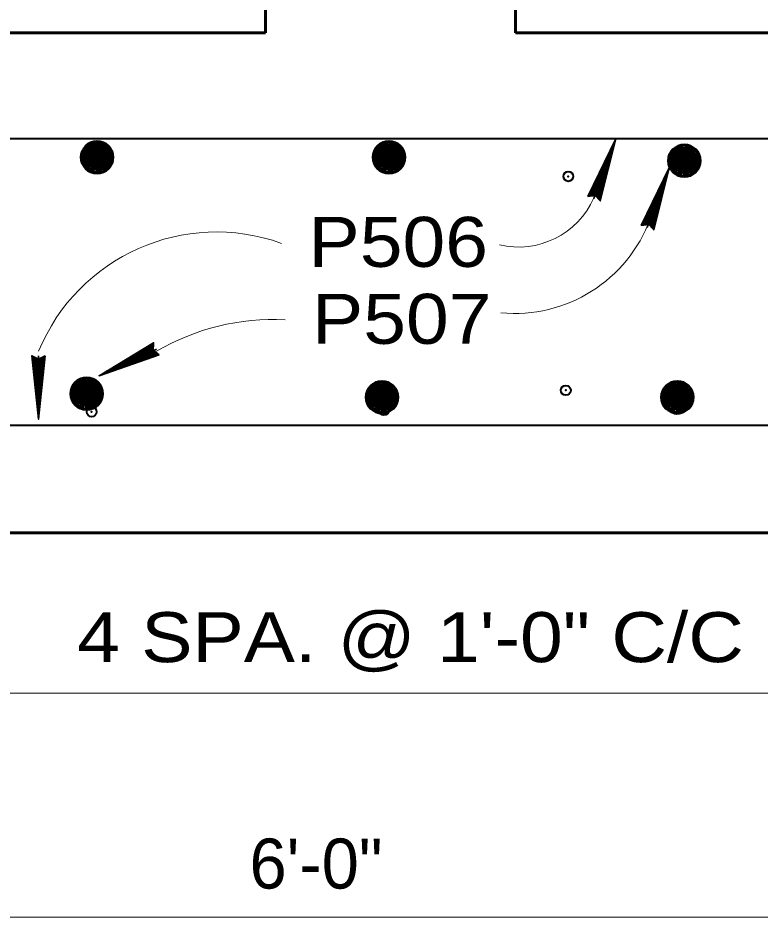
# Model space of a CAD drawing. Extents: x 14.14 to 17.34, y -1.61 to 0.38.
# Drawn here: x 15.611 to 15.7348, y -0.0793 to 0.0707 of the extents above; entities that cross this region are included whole.
import ezdxf

# ---------------------------------------------------------------- set-up
doc = ezdxf.new("R2010")
doc.units = 0
doc.header["$LTSCALE"] = 0.0033
doc.header["$PDMODE"] = 32
doc.header["$PDSIZE"] = 0.00165
doc.layers.add('1', color=7, linetype='Continuous', lineweight=40)

msp = doc.modelspace()

# ---------------------------------------------------------------- linework, layer by layer
at = {"layer": '1', "lineweight": 60}
for p, q in [((15.589833, 0.068167), (15.652333, 0.068167)), ((15.7565, 0.068167), (15.694, 0.068167)), ((15.622417, 0.049), (15.62225, 0.046083)), ((15.622667, 0.049), (15.622417, 0.046083)), ((15.622833, 0.049), (15.622667, 0.046)), ((15.623, 0.049), (15.62275, 0.046)), ((15.623167, 0.049), (15.623, 0.046)), ((15.623417, 0.049), (15.62325, 0.046)), ((15.623667, 0.049), (15.623417, 0.046)), ((15.62375, 0.048917), (15.623583, 0.046)), ((15.623917, 0.048917), (15.62375, 0.046)), ((15.624083, 0.048917), (15.623917, 0.046)), ((15.624333, 0.048917), (15.624083, 0.046)), ((15.6245, 0.048917), (15.624333, 0.046)), ((15.62475, 0.048833), (15.6245, 0.045917)), ((15.625, 0.048833), (15.62475, 0.045917)), ((15.625167, 0.048833), (15.625, 0.045917)), ((15.62525, 0.048833), (15.625083, 0.045917)), ((15.625417, 0.048833), (15.62525, 0.045917)), ((15.6255, 0.048833), (15.625333, 0.045917)), ((15.62575, 0.04875), (15.6255, 0.045833)), ((15.625917, 0.04875), (15.62575, 0.045833)), ((15.626083, 0.04875), (15.625833, 0.045833)), ((15.62625, 0.04875), (15.626083, 0.045833)), ((15.6265, 0.04875), (15.626333, 0.045833)), ((15.62675, 0.046833), (15.626583, 0.048667)), ((15.671083, 0.049), (15.670917, 0.046083)), ((15.671333, 0.049), (15.671083, 0.046083)), ((15.6715, 0.049), (15.671333, 0.046)), ((15.671667, 0.049), (15.671417, 0.046)), ((15.671833, 0.049), (15.671667, 0.046)), ((15.672083, 0.049), (15.671917, 0.046)), ((15.672333, 0.049), (15.672083, 0.046)), ((15.672417, 0.048917), (15.67225, 0.046)), ((15.672583, 0.048917), (15.672417, 0.046)), ((15.67275, 0.048917), (15.672583, 0.046)), ((15.673, 0.048917), (15.67275, 0.046)), ((15.673167, 0.048917), (15.673, 0.046)), ((15.673417, 0.048833), (15.673167, 0.045917)), ((15.673667, 0.048833), (15.673417, 0.045917)), ((15.673833, 0.048833), (15.673667, 0.045917)), ((15.673917, 0.048833), (15.67375, 0.045917)), ((15.674083, 0.048833), (15.673917, 0.045917)), ((15.674167, 0.048833), (15.674, 0.045917)), ((15.674417, 0.04875), (15.674167, 0.045833)), ((15.674583, 0.04875), (15.674417, 0.045833)), ((15.67475, 0.04875), (15.6745, 0.045833)), ((15.674917, 0.04875), (15.67475, 0.045833)), ((15.675167, 0.04875), (15.675, 0.045833)), ((15.675417, 0.046833), (15.67525, 0.048667)), ((15.720333, 0.048417), (15.720167, 0.0455)), ((15.720583, 0.048417), (15.720333, 0.0455)), ((15.72075, 0.048417), (15.720583, 0.045417)), ((15.720917, 0.048417), (15.720667, 0.045417)), ((15.721083, 0.048417), (15.720917, 0.045417)), ((15.721333, 0.048417), (15.721167, 0.045417)), ((15.721583, 0.048417), (15.721333, 0.045417)), ((15.721667, 0.048333), (15.7215, 0.045417)), ((15.721833, 0.048333), (15.721667, 0.045417)), ((15.722, 0.048333), (15.721833, 0.045417)), ((15.72225, 0.048333), (15.722, 0.045417)), ((15.722417, 0.048333), (15.72225, 0.045417)), ((15.722667, 0.04825), (15.722417, 0.045333)), ((15.722917, 0.04825), (15.722667, 0.045333)), ((15.723083, 0.04825), (15.722917, 0.045333)), ((15.723167, 0.04825), (15.723, 0.045333)), ((15.723333, 0.04825), (15.723167, 0.045333)), ((15.723417, 0.04825), (15.72325, 0.045333)), ((15.723667, 0.048167), (15.723417, 0.04525)), ((15.723833, 0.048167), (15.723667, 0.04525)), ((15.724, 0.048167), (15.72375, 0.04525)), ((15.724167, 0.048167), (15.724, 0.04525)), ((15.724417, 0.048167), (15.72425, 0.04525)), ((15.724667, 0.04625), (15.7245, 0.048083)), ((15.62675, 0.046833), (15.622, 0.046083)), ((15.675417, 0.046833), (15.670667, 0.046083)), ((15.724667, 0.04625), (15.719917, 0.0455)), ((15.620667, 0.009583), (15.6205, 0.006667)), ((15.620917, 0.009583), (15.620667, 0.006667)), ((15.621083, 0.009583), (15.620917, 0.006583)), ((15.62125, 0.009583), (15.621, 0.006583)), ((15.621417, 0.009583), (15.62125, 0.006583)), ((15.621667, 0.009583), (15.6215, 0.006583)), ((15.621917, 0.009583), (15.621667, 0.006583)), ((15.622, 0.0095), (15.621833, 0.006583)), ((15.622167, 0.0095), (15.622, 0.006583)), ((15.622333, 0.0095), (15.622167, 0.006583)), ((15.622583, 0.0095), (15.622333, 0.006583)), ((15.62275, 0.0095), (15.622583, 0.006583)), ((15.623, 0.009417), (15.62275, 0.0065)), ((15.62325, 0.009417), (15.623, 0.0065)), ((15.623417, 0.009417), (15.62325, 0.0065)), ((15.6235, 0.009417), (15.623333, 0.0065)), ((15.623667, 0.009417), (15.6235, 0.0065)), ((15.62375, 0.009417), (15.623583, 0.0065)), ((15.624, 0.009333), (15.62375, 0.006417)), ((15.624167, 0.009333), (15.624, 0.006417)), ((15.624333, 0.009333), (15.624083, 0.006417)), ((15.6245, 0.009333), (15.624333, 0.006417)), ((15.62475, 0.009333), (15.624583, 0.006417)), ((15.625, 0.007417), (15.624833, 0.00925)), ((15.669917, 0.009), (15.66975, 0.006083)), ((15.670167, 0.009), (15.669917, 0.006083)), ((15.670333, 0.009), (15.670167, 0.006)), ((15.6705, 0.009), (15.67025, 0.006)), ((15.670667, 0.009), (15.6705, 0.006)), ((15.670917, 0.009), (15.67075, 0.006)), ((15.671167, 0.009), (15.670917, 0.006)), ((15.719167, 0.009), (15.719, 0.006083)), ((15.719417, 0.009), (15.719167, 0.006083)), ((15.719583, 0.009), (15.719417, 0.006)), ((15.71975, 0.009), (15.7195, 0.006)), ((15.719917, 0.009), (15.71975, 0.006)), ((15.720167, 0.009), (15.72, 0.006)), ((15.720417, 0.009), (15.720167, 0.006)), ((15.67125, 0.008917), (15.671083, 0.006)), ((15.671417, 0.008917), (15.67125, 0.006)), ((15.671583, 0.008917), (15.671417, 0.006)), ((15.671833, 0.008917), (15.671583, 0.006)), ((15.672, 0.008917), (15.671833, 0.006)), ((15.67225, 0.008833), (15.672, 0.005917)), ((15.6725, 0.008833), (15.67225, 0.005917)), ((15.672667, 0.008833), (15.6725, 0.005917)), ((15.67275, 0.008833), (15.672583, 0.005917)), ((15.672917, 0.008833), (15.67275, 0.005917)), ((15.673, 0.008833), (15.672833, 0.005917)), ((15.67325, 0.00875), (15.673, 0.005833)), ((15.673417, 0.00875), (15.67325, 0.005833)), ((15.673583, 0.00875), (15.673333, 0.005833)), ((15.67375, 0.00875), (15.673583, 0.005833)), ((15.674, 0.00875), (15.673833, 0.005833)), ((15.67425, 0.006833), (15.674083, 0.008667)), ((15.7205, 0.008917), (15.720333, 0.006)), ((15.720667, 0.008917), (15.7205, 0.006)), ((15.720833, 0.008917), (15.720667, 0.006)), ((15.721083, 0.008917), (15.720833, 0.006)), ((15.72125, 0.008917), (15.721083, 0.006)), ((15.7215, 0.008833), (15.72125, 0.005917)), ((15.72175, 0.008833), (15.7215, 0.005917)), ((15.721917, 0.008833), (15.72175, 0.005917)), ((15.722, 0.008833), (15.721833, 0.005917)), ((15.722167, 0.008833), (15.722, 0.005917)), ((15.72225, 0.008833), (15.722083, 0.005917)), ((15.7225, 0.00875), (15.72225, 0.005833)), ((15.722667, 0.00875), (15.7225, 0.005833)), ((15.722833, 0.00875), (15.722583, 0.005833)), ((15.723, 0.00875), (15.722833, 0.005833)), ((15.72325, 0.00875), (15.723083, 0.005833)), ((15.7235, 0.006833), (15.723333, 0.008667)), ((15.625, 0.007417), (15.62025, 0.006667)), ((15.67425, 0.006833), (15.6695, 0.006083)), ((15.7235, 0.006833), (15.71875, 0.006083))]:
    msp.add_line(p, q, dxfattribs=at)
at = {"layer": '1'}
for p, q in [((15.524417, 0.050583), (15.822167, 0.050583)), ((15.6245, 0.0485), (15.625833, 0.0495)), ((15.626583, 0.048667), (15.625333, 0.049833)), ((15.673167, 0.0485), (15.6745, 0.0495)), ((15.67525, 0.048667), (15.674, 0.049833)), ((15.622167, 0.049), (15.62675, 0.046833)), ((15.622333, 0.048), (15.626167, 0.047333)), ((15.622417, 0.048583), (15.626333, 0.047833)), ((15.622417, 0.048417), (15.626333, 0.047667)), ((15.622417, 0.048167), (15.62625, 0.047417)), ((15.6225, 0.049), (15.626417, 0.048333)), ((15.6225, 0.048833), (15.626417, 0.048083)), ((15.622583, 0.049333), (15.626417, 0.048667)), ((15.670833, 0.049), (15.675417, 0.046833)), ((15.671, 0.048), (15.674833, 0.047333)), ((15.671083, 0.048583), (15.675, 0.047833)), ((15.671083, 0.048417), (15.675, 0.047667)), ((15.671083, 0.048167), (15.674917, 0.047417)), ((15.671167, 0.049), (15.675083, 0.048333)), ((15.671167, 0.048833), (15.675083, 0.048083)), ((15.67125, 0.049333), (15.675083, 0.048667)), ((15.720083, 0.048417), (15.724667, 0.04625)), ((15.720333, 0.048), (15.72425, 0.04725)), ((15.720417, 0.048417), (15.724333, 0.04775)), ((15.720417, 0.04825), (15.724333, 0.0475)), ((15.7205, 0.04875), (15.724333, 0.048083)), ((15.722417, 0.047917), (15.72375, 0.048917)), ((15.7245, 0.048083), (15.72325, 0.04925)), ((15.622083, 0.04675), (15.626, 0.046)), ((15.622083, 0.046583), (15.625917, 0.045833)), ((15.622167, 0.047167), (15.626083, 0.046417)), ((15.62225, 0.047583), (15.626083, 0.046833)), ((15.62225, 0.047417), (15.626083, 0.046667)), ((15.622333, 0.047833), (15.626167, 0.047083)), ((15.67075, 0.04675), (15.674667, 0.046)), ((15.67075, 0.046583), (15.674583, 0.045833)), ((15.670833, 0.047167), (15.67475, 0.046417)), ((15.670917, 0.047583), (15.67475, 0.046833)), ((15.670917, 0.047417), (15.67475, 0.046667)), ((15.671, 0.047833), (15.674833, 0.047083)), ((15.720083, 0.046583), (15.724, 0.045833)), ((15.720167, 0.047), (15.724, 0.04625)), ((15.720167, 0.046833), (15.724, 0.046083)), ((15.72025, 0.047417), (15.724083, 0.04675)), ((15.72025, 0.04725), (15.724083, 0.0465)), ((15.720333, 0.047833), (15.72425, 0.047083)), ((15.720333, 0.047583), (15.724167, 0.046833)), ((15.622, 0.04625), (15.625833, 0.0455)), ((15.622, 0.046083), (15.625833, 0.045333)), ((15.622083, 0.046333), (15.625917, 0.045667)), ((15.626333, 0.045833), (15.622583, 0.045417)), ((15.670667, 0.04625), (15.6745, 0.0455)), ((15.670667, 0.046083), (15.6745, 0.045333)), ((15.67075, 0.046333), (15.674583, 0.045667)), ((15.675, 0.045833), (15.67125, 0.045417)), ((15.719917, 0.045667), (15.72375, 0.044917)), ((15.719917, 0.0455), (15.72375, 0.04475)), ((15.72, 0.046167), (15.723917, 0.045417)), ((15.72, 0.046), (15.723833, 0.04525)), ((15.72, 0.04575), (15.723833, 0.045083)), ((15.72425, 0.04525), (15.7205, 0.044833)), ((15.620417, 0.009583), (15.625, 0.007417)), ((15.620667, 0.009167), (15.624583, 0.008417)), ((15.620667, 0.009), (15.624583, 0.00825)), ((15.62075, 0.009583), (15.624667, 0.008917)), ((15.62075, 0.009417), (15.624667, 0.008667)), ((15.620833, 0.009917), (15.624667, 0.00925)), ((15.62275, 0.009083), (15.624083, 0.010083)), ((15.624833, 0.00925), (15.623583, 0.010417)), ((15.669667, 0.009), (15.67425, 0.006833)), ((15.67, 0.009), (15.673917, 0.008333)), ((15.670083, 0.009333), (15.673917, 0.008667)), ((15.672, 0.0085), (15.673333, 0.0095)), ((15.674083, 0.008667), (15.672833, 0.009833)), ((15.718917, 0.009), (15.7235, 0.006833)), ((15.71925, 0.009), (15.723167, 0.008333)), ((15.719333, 0.009333), (15.723167, 0.008667)), ((15.72125, 0.0085), (15.722583, 0.0095)), ((15.723333, 0.008667), (15.722083, 0.009833)), ((15.620417, 0.00775), (15.624333, 0.007)), ((15.6205, 0.008167), (15.624333, 0.007417)), ((15.6205, 0.008), (15.624333, 0.00725)), ((15.620583, 0.008583), (15.624417, 0.007917)), ((15.620583, 0.008417), (15.624417, 0.007667)), ((15.620667, 0.00875), (15.6245, 0.008)), ((15.66975, 0.007583), (15.673583, 0.006833)), ((15.669833, 0.008), (15.673667, 0.007333)), ((15.669833, 0.007833), (15.673667, 0.007083)), ((15.669917, 0.008583), (15.673833, 0.007833)), ((15.669917, 0.008417), (15.673833, 0.007667)), ((15.669917, 0.008167), (15.67375, 0.007417)), ((15.67, 0.008833), (15.673917, 0.008083)), ((15.719, 0.007583), (15.722833, 0.006833)), ((15.719083, 0.008), (15.722917, 0.007333)), ((15.719083, 0.007833), (15.722917, 0.007083)), ((15.719167, 0.008583), (15.723083, 0.007833)), ((15.719167, 0.008417), (15.723083, 0.007667)), ((15.719167, 0.008167), (15.723, 0.007417)), ((15.71925, 0.008833), (15.723167, 0.008083)), ((15.62025, 0.006833), (15.624083, 0.006083)), ((15.62025, 0.006667), (15.624083, 0.005917)), ((15.620333, 0.007333), (15.62425, 0.006583)), ((15.620333, 0.007167), (15.624167, 0.006417)), ((15.620333, 0.006917), (15.624167, 0.00625)), ((15.624583, 0.006417), (15.620833, 0.006)), ((15.6695, 0.00625), (15.673333, 0.0055)), ((15.6695, 0.006083), (15.673333, 0.005333)), ((15.669583, 0.00675), (15.6735, 0.006)), ((15.669583, 0.006583), (15.673417, 0.005833)), ((15.669583, 0.006333), (15.673417, 0.005667)), ((15.669667, 0.007167), (15.673583, 0.006417)), ((15.66975, 0.007417), (15.673583, 0.006667)), ((15.71875, 0.00625), (15.722583, 0.0055)), ((15.71875, 0.006083), (15.722583, 0.005333)), ((15.718833, 0.00675), (15.72275, 0.006)), ((15.718833, 0.006583), (15.722667, 0.005833)), ((15.718833, 0.006333), (15.722667, 0.005667)), ((15.718917, 0.007167), (15.722833, 0.006417)), ((15.719, 0.007417), (15.722833, 0.006667)), ((15.673833, 0.005833), (15.670083, 0.005417)), ((15.723083, 0.005833), (15.719333, 0.005417)), ((15.52425, 0.00275), (15.821917, 0.00275))]:
    msp.add_line(p, q, dxfattribs=at)
at = {"layer": '1', "lineweight": 35}
for p, q in [((15.707083, 0.040583), (15.71075, 0.0505)), ((15.70625, 0.041083), (15.70975, 0.048167)), ((15.70625, 0.041083), (15.70975, 0.048167)), ((15.706333, 0.041083), (15.70975, 0.048167)), ((15.706417, 0.041083), (15.709833, 0.048167)), ((15.706417, 0.041083), (15.71, 0.048083)), ((15.70775, 0.0405), (15.709583, 0.047583)), ((15.708, 0.0405), (15.709667, 0.047667)), ((15.708, 0.0405), (15.709833, 0.047583)), ((15.708167, 0.040417), (15.709917, 0.047583)), ((15.716, 0.03575), (15.719667, 0.045667)), ((15.715167, 0.03625), (15.718667, 0.043333)), ((15.715167, 0.03625), (15.718667, 0.043333)), ((15.71525, 0.03625), (15.718667, 0.043333)), ((15.715333, 0.03625), (15.71875, 0.043333)), ((15.715333, 0.03625), (15.718917, 0.04325)), ((15.716667, 0.035667), (15.7185, 0.04275)), ((15.716917, 0.035667), (15.718583, 0.042833)), ((15.716917, 0.035667), (15.71875, 0.04275)), ((15.717083, 0.035583), (15.718833, 0.04275)), ((15.634167, 0.015417), (15.624583, 0.011)), ((15.6335, 0.016333), (15.627167, 0.0125)), ((15.6335, 0.016167), (15.627167, 0.012417)), ((15.633583, 0.016083), (15.62725, 0.01225)), ((15.63375, 0.016), (15.627417, 0.01225)), ((15.613417, 0.014083), (15.61425, 0.00675)), ((15.613583, 0.014083), (15.614333, 0.00675)), ((15.613667, 0.014083), (15.6145, 0.00675)), ((15.613833, 0.014167), (15.614583, 0.006833)), ((15.615333, 0.014083), (15.614333, 0.00625)), ((15.6145, 0.014333), (15.6145, 0.00375)), ((15.615333, 0.014083), (15.6145, 0.00625)), ((15.6155, 0.014083), (15.614583, 0.00625)), ((15.6155, 0.014083), (15.614583, 0.00625)), ((15.615417, 0.014083), (15.614583, 0.00625)), ((15.63425, 0.014583), (15.62675, 0.012167)), ((15.63425, 0.014583), (15.626833, 0.012)), ((15.634333, 0.0145), (15.626833, 0.012)), ((15.634333, 0.014417), (15.626833, 0.012)), ((15.634333, 0.014417), (15.626833, 0.012))]:
    msp.add_line(p, q, dxfattribs=at)
at = {"layer": '1', "lineweight": 13}
for p, q in [((15.523583, -0.041917), (15.820833, -0.041917)), ((15.511083, -0.07925), (15.837333, -0.07925))]:
    msp.add_line(p, q, dxfattribs=at)
at = {"layer": '1', "lineweight": 60}
for points in [[(15.652333, 0.068167), (15.652333, 0.089), (15.694, 0.089), (15.694, 0.068167)], [(15.839833, 0.068167), (15.839833, -0.015167), (15.5065, -0.015167)], [(15.625833, 0.045333), (15.625833, 0.0495), (15.624167, 0.044833), (15.624667, 0.05), (15.622583, 0.045417), (15.623333, 0.049917), (15.624917, 0.044917), (15.62175, 0.04825), (15.626583, 0.048667), (15.623333, 0.045), (15.625333, 0.049833), (15.622167, 0.049), (15.622, 0.046083)], [(15.622583, 0.045417), (15.624083, 0.047667), (15.621917, 0.048583), (15.623917, 0.05), (15.624083, 0.04775), (15.62575, 0.045417), (15.62175, 0.04775), (15.6245, 0.0485)], [(15.625333, 0.049833), (15.624083, 0.047667), (15.626333, 0.045833)], [(15.6745, 0.045333), (15.6745, 0.0495), (15.672833, 0.044833), (15.673333, 0.05), (15.67125, 0.045417), (15.672, 0.049917), (15.673583, 0.044917), (15.670417, 0.04825), (15.67525, 0.048667), (15.672, 0.045), (15.674, 0.049833), (15.670833, 0.049), (15.670667, 0.046083)], [(15.67125, 0.045417), (15.67275, 0.047667), (15.670583, 0.048583), (15.672583, 0.05), (15.67275, 0.04775), (15.674417, 0.045417), (15.670417, 0.04775), (15.673167, 0.0485)], [(15.674, 0.049833), (15.67275, 0.047667), (15.675, 0.045833)], [(15.621583, 0.047333), (15.62675, 0.048), (15.622167, 0.049)], [(15.67025, 0.047333), (15.675417, 0.048), (15.670833, 0.049)], [(15.7195, 0.04675), (15.724667, 0.047417), (15.720083, 0.048417)], [(15.72375, 0.04475), (15.72375, 0.048917), (15.722083, 0.04425), (15.722583, 0.049417), (15.7205, 0.044833), (15.72125, 0.049333), (15.722833, 0.044333), (15.719667, 0.047667), (15.7245, 0.048083), (15.72125, 0.044417), (15.72325, 0.04925), (15.720083, 0.048417), (15.719917, 0.0455)], [(15.7205, 0.044833), (15.722, 0.047083), (15.719833, 0.048), (15.721833, 0.049417), (15.722, 0.047167), (15.723667, 0.044833), (15.719667, 0.047167), (15.722417, 0.047917)], [(15.72325, 0.04925), (15.722, 0.047083), (15.72425, 0.04525)], [(15.624083, 0.005917), (15.624083, 0.010083), (15.622417, 0.005417), (15.622917, 0.010583), (15.620833, 0.006), (15.621583, 0.0105), (15.623167, 0.0055), (15.62, 0.008833), (15.624833, 0.00925), (15.621583, 0.005583), (15.623583, 0.010417), (15.620417, 0.009583), (15.62025, 0.006667)], [(15.620833, 0.006), (15.622333, 0.00825), (15.620167, 0.009167), (15.622167, 0.010583), (15.622333, 0.008333), (15.624, 0.006), (15.62, 0.008333), (15.62275, 0.009083)], [(15.619833, 0.007917), (15.625, 0.008583), (15.620417, 0.009583)], [(15.623583, 0.010417), (15.622333, 0.00825), (15.624583, 0.006417)], [(15.669083, 0.007333), (15.67425, 0.008), (15.669667, 0.009)], [(15.673333, 0.005333), (15.673333, 0.0095), (15.671667, 0.004833), (15.672167, 0.01), (15.670083, 0.005417), (15.670833, 0.009917), (15.672417, 0.004917), (15.66925, 0.00825), (15.674083, 0.008667), (15.670833, 0.005), (15.672833, 0.009833), (15.669667, 0.009), (15.6695, 0.006083)], [(15.670083, 0.005417), (15.671583, 0.007667), (15.669417, 0.008583), (15.671417, 0.01), (15.671583, 0.00775), (15.67325, 0.005417), (15.66925, 0.00775), (15.672, 0.0085)], [(15.672833, 0.009833), (15.671583, 0.007667), (15.673833, 0.005833)], [(15.718333, 0.007333), (15.7235, 0.008), (15.718917, 0.009)], [(15.722583, 0.005333), (15.722583, 0.0095), (15.720917, 0.004833), (15.721417, 0.01), (15.719333, 0.005417), (15.720083, 0.009917), (15.721667, 0.004917), (15.7185, 0.00825), (15.723333, 0.008667), (15.720083, 0.005), (15.722083, 0.009833), (15.718917, 0.009), (15.71875, 0.006083)], [(15.719333, 0.005417), (15.720833, 0.007667), (15.718667, 0.008583), (15.720667, 0.01), (15.720833, 0.00775), (15.7225, 0.005417), (15.7185, 0.00775), (15.72125, 0.0085)], [(15.722083, 0.009833), (15.720833, 0.007667), (15.723083, 0.005833)]]:
    msp.add_lwpolyline(points, dxfattribs=at)
at = {"layer": '1', "lineweight": 35}
for points in [[(15.706083, 0.040917), (15.71075, 0.0505), (15.708167, 0.040167), (15.707333, 0.041083)], [(15.70725, 0.04125), (15.70875, 0.045667), (15.708833, 0.045667), (15.708583, 0.044833), (15.707167, 0.041333), (15.708167, 0.044167), (15.707, 0.04125), (15.707667, 0.043333), (15.706833, 0.04125), (15.70825, 0.0445), (15.71, 0.048833), (15.709917, 0.047833), (15.710333, 0.049), (15.7075, 0.041167), (15.7085, 0.043417), (15.707583, 0.041), (15.709, 0.046167), (15.707833, 0.040917)], [(15.715, 0.036083), (15.719667, 0.045667), (15.717083, 0.035333), (15.71625, 0.03625)], [(15.716167, 0.036417), (15.717667, 0.040833), (15.71775, 0.040833), (15.7175, 0.04), (15.716083, 0.0365), (15.717083, 0.039333), (15.715917, 0.036417), (15.716583, 0.0385), (15.71575, 0.036417), (15.717167, 0.039667), (15.718917, 0.044), (15.718833, 0.043), (15.71925, 0.044167), (15.716417, 0.036333), (15.717417, 0.038583), (15.7165, 0.036167), (15.717917, 0.041333), (15.71675, 0.036083)], [(15.634583, 0.0145), (15.624583, 0.011), (15.633667, 0.0165), (15.633583, 0.01525)], [(15.6335, 0.015083), (15.629333, 0.013), (15.62925, 0.013083), (15.630083, 0.0135), (15.6335, 0.015), (15.630833, 0.013667), (15.63375, 0.014917), (15.63175, 0.013917), (15.633833, 0.01475), (15.630583, 0.0135), (15.62625, 0.011667), (15.627, 0.012333), (15.625833, 0.01175), (15.633417, 0.01525), (15.631167, 0.014417), (15.6335, 0.0155), (15.628833, 0.012917), (15.633333, 0.01575)], [(15.615583, 0.014333), (15.6145, 0.00375), (15.613333, 0.014333), (15.6145, 0.01375)], [(15.614583, 0.013583), (15.614667, 0.008917), (15.614583, 0.008917), (15.614583, 0.009833), (15.614667, 0.013583), (15.61475, 0.010583), (15.614833, 0.01375), (15.614917, 0.0115), (15.615, 0.01375), (15.61475, 0.01025), (15.614583, 0.005583), (15.614333, 0.0065), (15.614333, 0.00525), (15.614333, 0.013583), (15.614167, 0.011167), (15.614167, 0.01375), (15.614583, 0.008417), (15.613917, 0.01375)]]:
    msp.add_lwpolyline(points, close=True, dxfattribs=at)
at = {"layer": '1'}
for points in [[(15.622, 0.046083), (15.624083, 0.044833), (15.625833, 0.045333), (15.62675, 0.046833)], [(15.670667, 0.046083), (15.67275, 0.044833), (15.6745, 0.045333), (15.675417, 0.046833)], [(15.719917, 0.0455), (15.722, 0.04425), (15.72375, 0.04475), (15.724667, 0.04625)], [(15.62025, 0.006667), (15.622333, 0.005417), (15.624083, 0.005917), (15.625, 0.007417)], [(15.6695, 0.006083), (15.671583, 0.004833), (15.673333, 0.005333), (15.67425, 0.006833)], [(15.71875, 0.006083), (15.720833, 0.004833), (15.722583, 0.005333), (15.7235, 0.006833)]]:
    msp.add_lwpolyline(points, dxfattribs=at)
at = {"layer": '1', "lineweight": 35}
for points in [[(15.70725, 0.04125), (15.706417, 0.041167), (15.70675, 0.041333), (15.707083, 0.041333), (15.707083, 0.041583), (15.70675, 0.041583), (15.707417, 0.041167), (15.707833, 0.040833), (15.708083, 0.040417)], [(15.716167, 0.036417), (15.715333, 0.036333), (15.715667, 0.0365), (15.716, 0.0365), (15.716, 0.03675), (15.715667, 0.03675), (15.716333, 0.036333), (15.71675, 0.036), (15.717, 0.035583)], [(15.6335, 0.015083), (15.634167, 0.014583), (15.633833, 0.014667), (15.633583, 0.014917), (15.633417, 0.01475), (15.633667, 0.0145), (15.6335, 0.01525), (15.633417, 0.01575), (15.6335, 0.01625)], [(15.614583, 0.013583), (15.615333, 0.014), (15.615083, 0.01375), (15.61475, 0.013583), (15.614833, 0.013333), (15.615167, 0.0135), (15.614417, 0.013667), (15.613917, 0.013833), (15.6135, 0.014083)]]:
    msp.add_lwpolyline(points, dxfattribs=at)
at = {"layer": '1', "lineweight": 60}
for centre in [(15.62425, 0.047433), (15.672917, 0.047433), (15.722167, 0.04685), (15.6225, 0.008017), (15.67175, 0.007433), (15.721, 0.007433)]:
    msp.add_circle(centre, 0.00264, dxfattribs=at)
at = {"layer": '1', "lineweight": 13}
for centre, radius, start, end in [((15.694494, 0.046229), 0.013764, 256.72512, 336.1622), ((15.693857, 0.045532), 0.024139, 264.5959, 339.72439), ((15.644136, 0.002964), 0.032019, 70.16671, 157.75827), ((15.65357, -0.017761), 0.038147, 86.97419, 120.57314)]:
    msp.add_arc(centre, radius, start, end, dxfattribs=at)
at = {"layer": '1'}
for p in [(15.624667, 0.046583), (15.722417, 0.04675), (15.702833, 0.04425), (15.702417, 0.008583), (15.672083, 0.00525), (15.720917, 0.005417), (15.623333, 0.005)]:
    msp.add_point(p, dxfattribs=at)

# ---------------------------------------------------------------- texts
at = {"layer": '1', "width": 1.15}
for s, p in [('P506', (15.6595, 0.029167)), ('P507', (15.660083, 0.016333)), ('4 SPA. @ 1\'-0" C/C', (15.620917, -0.03675))]:
    msp.add_text(s, height=0.008334, dxfattribs=at).set_placement(p)
at = {"layer": '1'}
msp.add_text('6\'-0"', height=0.008333, dxfattribs=at).set_placement((15.649667, -0.0745))

doc.saveas('drawing.dxf')
